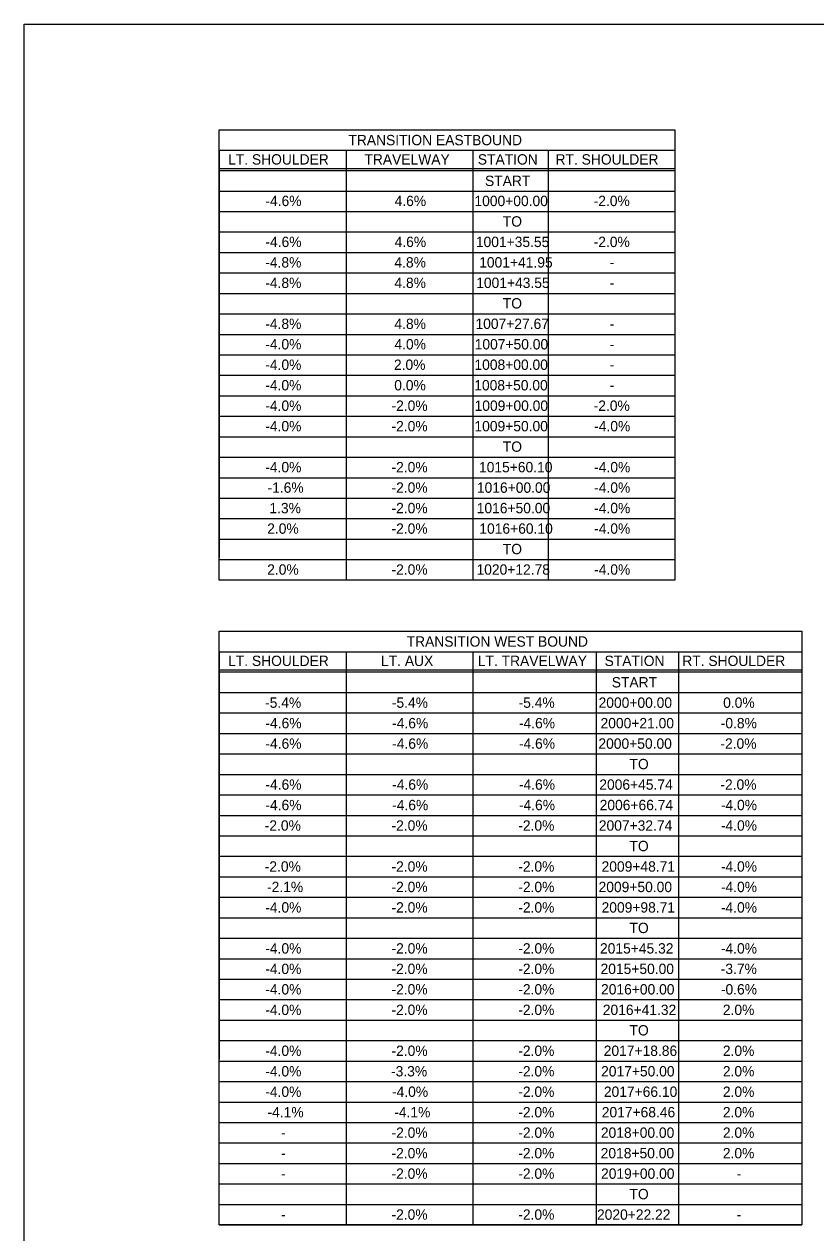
# Model space of a CAD drawing. Extents: x -15319374 to 1762012, y 465773 to 3693661.
# Drawn here: x -15314452.8 to -15314223.1, y 3693309.9 to 3693660.7 of the extents above; entities that cross this region are included whole.
import ezdxf

# ---------------------------------------------------------------- set-up
doc = ezdxf.new("R2010")
doc.units = 0
for name, color, linetype in [('BORDER', 7, 'Continuous'), ('Default', 7, 'Continuous'), ('DIMENSIONS', 7, 'Continuous')]:
    doc.layers.add(name, color=color, linetype=linetype)

msp = doc.modelspace()

# ---------------------------------------------------------------- linework, layer by layer
at = {"layer": 'BORDER'}
for p, q in [((-15314396.16, 3693624.08), (-15314396.16, 3693505.88)), ((-15314359.39, 3693624.08), (-15314359.39, 3693499.35)), ((-15314322.62, 3693624.08), (-15314322.62, 3693499.35)), ((-15314300.75, 3693624.08), (-15314300.75, 3693499.35)), ((-15314396.16, 3693618.8), (-15314263.98, 3693618.8)), ((-15314396.16, 3693618.2), (-15314263.98, 3693618.2)), ((-15314396.16, 3693612.26), (-15314263.98, 3693612.26)), ((-15314396.16, 3693612.26), (-15314263.98, 3693612.26)), ((-15314396.16, 3693612.26), (-15314263.98, 3693612.26)), ((-15314396.16, 3693606.32), (-15314263.98, 3693606.32)), ((-15314396.16, 3693600.38), (-15314263.98, 3693600.38)), ((-15314396.16, 3693594.43), (-15314263.98, 3693594.43)), ((-15314396.16, 3693588.49), (-15314263.98, 3693588.49)), ((-15314396.16, 3693582.55), (-15314263.98, 3693582.55)), ((-15314396.16, 3693576.6), (-15314263.98, 3693576.6)), ((-15314396.16, 3693570.66), (-15314263.98, 3693570.66)), ((-15314396.16, 3693564.72), (-15314263.98, 3693564.72)), ((-15314396.16, 3693558.78), (-15314263.98, 3693558.78)), ((-15314396.16, 3693552.83), (-15314263.98, 3693552.83)), ((-15314396.16, 3693546.89), (-15314263.98, 3693546.89)), ((-15314396.16, 3693540.95), (-15314263.98, 3693540.95)), ((-15314396.16, 3693535.01), (-15314263.98, 3693535.01)), ((-15314396.16, 3693529.06), (-15314263.98, 3693529.06)), ((-15314396.16, 3693523.12), (-15314263.98, 3693523.12)), ((-15314396.16, 3693517.18), (-15314263.98, 3693517.18)), ((-15314396.16, 3693511.24), (-15314263.98, 3693511.24)), ((-15314396.16, 3693505.29), (-15314263.98, 3693505.29)), ((-15314396.16, 3693478.56), (-15314396.16, 3693360.36)), ((-15314359.39, 3693478.56), (-15314359.39, 3693312.23)), ((-15314322.62, 3693478.56), (-15314322.62, 3693312.23)), ((-15314286.85, 3693478.56), (-15314286.85, 3693312.23)), ((-15314262.98, 3693478.56), (-15314262.98, 3693312.23)), ((-15314396.16, 3693473.28), (-15314227.21, 3693473.28)), ((-15314396.16, 3693472.68), (-15314227.21, 3693472.68)), ((-15314396.16, 3693466.74), (-15314227.21, 3693466.74)), ((-15314396.16, 3693466.74), (-15314227.21, 3693466.74)), ((-15314396.16, 3693466.74), (-15314227.21, 3693466.74)), ((-15314396.16, 3693460.8), (-15314227.21, 3693460.8)), ((-15314396.16, 3693454.85), (-15314227.21, 3693454.85)), ((-15314396.16, 3693448.91), (-15314227.21, 3693448.91)), ((-15314396.16, 3693442.97), (-15314227.21, 3693442.97)), ((-15314396.16, 3693437.02), (-15314227.21, 3693437.02)), ((-15314396.16, 3693431.08), (-15314227.21, 3693431.08)), ((-15314396.16, 3693425.14), (-15314227.21, 3693425.14)), ((-15314396.16, 3693419.2), (-15314227.21, 3693419.2)), ((-15314396.16, 3693413.25), (-15314227.21, 3693413.25)), ((-15314396.16, 3693407.31), (-15314227.21, 3693407.31)), ((-15314396.16, 3693401.37), (-15314227.21, 3693401.37)), ((-15314396.16, 3693395.43), (-15314227.21, 3693395.43)), ((-15314396.16, 3693389.48), (-15314227.21, 3693389.48)), ((-15314396.16, 3693383.54), (-15314227.21, 3693383.54)), ((-15314396.16, 3693377.6), (-15314227.21, 3693377.6)), ((-15314396.16, 3693371.66), (-15314227.21, 3693371.66)), ((-15314396.16, 3693365.71), (-15314227.21, 3693365.71)), ((-15314396.16, 3693359.77), (-15314227.21, 3693359.77)), ((-15314396.16, 3693353.83), (-15314227.21, 3693353.83)), ((-15314396.16, 3693347.88), (-15314227.21, 3693347.88)), ((-15314396.16, 3693341.94), (-15314227.21, 3693341.94)), ((-15314396.16, 3693336), (-15314227.21, 3693336)), ((-15314396.16, 3693330.06), (-15314227.21, 3693330.06)), ((-15314396.16, 3693324.11), (-15314227.21, 3693324.11)), ((-15314396.16, 3693318.17), (-15314227.21, 3693318.17)), ((-15314396.16, 3693312.23), (-15314227.21, 3693312.23))]:
    msp.add_line(p, q, dxfattribs=at)
for points in [[(-15314396.16, 3693624.08), (-15314396.16, 3693630.02), (-15314263.98, 3693630.02), (-15314263.98, 3693624.08)], [(-15314396.16, 3693478.56), (-15314396.16, 3693484.5), (-15314227.21, 3693484.5), (-15314227.21, 3693478.56)]]:
    msp.add_lwpolyline(points, dxfattribs=at)
for points in [[(-15314396.16, 3693624.08), (-15314263.98, 3693624.08), (-15314263.98, 3693499.35), (-15314396.16, 3693499.35)], [(-15314396.16, 3693478.56), (-15314227.21, 3693478.56), (-15314227.21, 3693312.23), (-15314396.16, 3693312.23)]]:
    msp.add_lwpolyline(points, close=True, dxfattribs=at)
at = {"layer": 'Default'}
msp.add_lwpolyline([(-15314452.76, 3693660.68), (-15313582.2, 3693660.68), (-15313582.2, 3693071.2), (-15314452.76, 3693071.2)], close=True, dxfattribs=at)

# ---------------------------------------------------------------- texts
at = {"layer": 'DIMENSIONS'}
for s, p in [('TRANSITION EASTBOUND', (-15314358.71, 3693625.55)), ('LT. SHOULDER', (-15314393.6, 3693619.94)), ('TRAVELWAY', (-15314354.06, 3693619.94)), ('STATION', (-15314321.16, 3693619.94)), ('RT. SHOULDER', (-15314298.62, 3693619.94)), ('START', (-15314319.08, 3693613.72)), ('-4.6%', (-15314382.78, 3693607.89)), ('4.6%', (-15314345.3, 3693607.89)), ('1000+00.00', (-15314322.14, 3693607.89)), ('-2.0%', (-15314287.56, 3693607.89)), ('TO', (-15314313.92, 3693601.94)), ('-4.6%', (-15314382.78, 3693596)), ('4.6%', (-15314345.3, 3693596)), ('1001+35.55', (-15314321.73, 3693596)), ('-2.0%', (-15314287.56, 3693596)), ('-4.8%', (-15314382.82, 3693590.06)), ('4.8%', (-15314345.35, 3693590.06)), ('1001+41.95', (-15314320.76, 3693590.06)), ('-', (-15314282.87, 3693590.06)), ('-4.8%', (-15314382.82, 3693584.12)), ('4.8%', (-15314345.35, 3693584.12)), ('1001+43.55', (-15314321.63, 3693584.12)), ('-', (-15314282.87, 3693584.12)), ('TO', (-15314313.92, 3693578.17)), ('-4.8%', (-15314382.82, 3693572.23)), ('4.8%', (-15314345.35, 3693572.23)), ('1007+27.67', (-15314321.84, 3693572.23)), ('-', (-15314282.87, 3693572.23)), ('-4.0%', (-15314382.82, 3693566.29)), ('4.0%', (-15314345.35, 3693566.29)), ('1007+50.00', (-15314322.07, 3693566.29)), ('-', (-15314282.87, 3693566.29)), ('-4.0%', (-15314382.82, 3693560.35)), ('2.0%', (-15314345.49, 3693560.35)), ('1008+00.00', (-15314322.14, 3693560.35)), ('-', (-15314282.87, 3693560.35)), ('-4.0%', (-15314382.82, 3693554.4)), ('0.0%', (-15314345.4, 3693554.4)), ('1008+50.00', (-15314322.19, 3693554.4)), ('-', (-15314282.87, 3693554.4)), ('-4.0%', (-15314382.82, 3693548.46)), ('-2.0%', (-15314346.2, 3693548.46)), ('1009+00.00', (-15314322.1, 3693548.46)), ('-2.0%', (-15314287.56, 3693548.46)), ('-4.0%', (-15314382.82, 3693542.52)), ('-2.0%', (-15314346.2, 3693542.52)), ('1009+50.00', (-15314322.14, 3693542.52)), ('-4.0%', (-15314287.41, 3693542.52)), ('TO', (-15314313.92, 3693536.58)), ('-4.0%', (-15314382.82, 3693530.63)), ('-2.0%', (-15314346.2, 3693530.63)), ('1015+60.10', (-15314320.82, 3693530.63)), ('-4.0%', (-15314287.41, 3693530.63)), ('-1.6%', (-15314382.16, 3693524.69)), ('-2.0%', (-15314346.2, 3693524.69)), ('1016+00.00', (-15314321.43, 3693524.69)), ('-4.0%', (-15314287.41, 3693524.69)), ('1.3%', (-15314381.62, 3693518.75)), ('-2.0%', (-15314346.2, 3693518.75)), ('1016+50.00', (-15314321.48, 3693518.75)), ('-4.0%', (-15314287.41, 3693518.75)), ('2.0%', (-15314382.26, 3693512.8)), ('-2.0%', (-15314346.2, 3693512.8)), ('1016+60.10', (-15314320.72, 3693512.8)), ('-4.0%', (-15314287.41, 3693512.8)), ('TO', (-15314313.92, 3693506.86)), ('2.0%', (-15314382.26, 3693500.92)), ('-2.0%', (-15314346.2, 3693500.92)), ('1020+12.78', (-15314321.54, 3693500.92)), ('-4.0%', (-15314287.41, 3693500.92)), ('TRANSITION WEST BOUND', (-15314341.81, 3693480.03)), ('LT. SHOULDER', (-15314393.6, 3693474.42)), ('LT. AUX', (-15314349.24, 3693474.42)), ('LT. TRAVELWAY', (-15314321.17, 3693474.42)), ('STATION', (-15314284.39, 3693474.42)), ('RT. SHOULDER', (-15314261.85, 3693474.42)), ('START', (-15314282.31, 3693468.19)), ('-5.4%', (-15314382.87, 3693462.28)), ('-5.4%', (-15314346.1, 3693462.28)), ('-5.4%', (-15314309.34, 3693462.28)), ('2000+00.00', (-15314286.13, 3693462.28)), ('0.0%', (-15314249.99, 3693462.28)), ('-4.6%', (-15314382.78, 3693456.34)), ('-4.6%', (-15314346.01, 3693456.34)), ('-4.6%', (-15314309.24, 3693456.34)), ('2000+21.00', (-15314285.56, 3693456.34)), ('-0.8%', (-15314250.69, 3693456.34)), ('-4.6%', (-15314382.78, 3693450.4)), ('-4.6%', (-15314346.01, 3693450.4)), ('-4.6%', (-15314309.24, 3693450.4)), ('2000+50.00', (-15314286.18, 3693450.4)), ('-2.0%', (-15314250.79, 3693450.4)), ('TO', (-15314277.16, 3693444.46)), ('-4.6%', (-15314382.78, 3693438.51)), ('-4.6%', (-15314346.01, 3693438.51)), ('-4.6%', (-15314309.24, 3693438.51)), ('2006+45.74', (-15314285.92, 3693438.51)), ('-2.0%', (-15314250.79, 3693438.51)), ('-4.6%', (-15314382.78, 3693432.57)), ('-4.6%', (-15314346.01, 3693432.57)), ('-4.6%', (-15314309.24, 3693432.57)), ('2006+66.74', (-15314285.82, 3693432.57)), ('-4.0%', (-15314250.65, 3693432.57)), ('-2.0%', (-15314382.97, 3693426.63)), ('-2.0%', (-15314346.2, 3693426.63)), ('-2.0%', (-15314309.43, 3693426.63)), ('2007+32.74', (-15314286.06, 3693426.63)), ('-4.0%', (-15314250.65, 3693426.63)), ('TO', (-15314277.16, 3693420.68)), ('-2.0%', (-15314382.97, 3693414.74)), ('-2.0%', (-15314346.2, 3693414.74)), ('-2.0%', (-15314309.43, 3693414.74)), ('2009+48.71', (-15314285.26, 3693414.74)), ('-4.0%', (-15314250.65, 3693414.74)), ('-2.1%', (-15314382.31, 3693408.8)), ('-2.0%', (-15314346.2, 3693408.8)), ('-2.0%', (-15314309.43, 3693408.8)), ('2009+50.00', (-15314286.13, 3693408.8)), ('-4.0%', (-15314250.65, 3693408.8)), ('-4.0%', (-15314382.82, 3693402.86)), ('-2.0%', (-15314346.2, 3693402.86)), ('-2.0%', (-15314309.43, 3693402.86)), ('2009+98.71', (-15314285.26, 3693402.86)), ('-4.0%', (-15314250.65, 3693402.86)), ('TO', (-15314277.16, 3693396.91)), ('-4.0%', (-15314382.82, 3693390.97)), ('-2.0%', (-15314346.2, 3693390.97)), ('-2.0%', (-15314309.43, 3693390.97)), ('2015+45.32', (-15314285.72, 3693390.97)), ('-4.0%', (-15314250.65, 3693390.97)), ('-4.0%', (-15314382.82, 3693385.03)), ('-2.0%', (-15314346.2, 3693385.03)), ('-2.0%', (-15314309.43, 3693385.03)), ('2015+50.00', (-15314285.56, 3693385.03)), ('-3.7%', (-15314250.69, 3693385.03)), ('-4.0%', (-15314382.82, 3693379.09)), ('-2.0%', (-15314346.2, 3693379.09)), ('-2.0%', (-15314309.43, 3693379.09)), ('2016+00.00', (-15314285.42, 3693379.09)), ('-0.6%', (-15314250.65, 3693379.09)), ('-4.0%', (-15314382.82, 3693373.14)), ('-2.0%', (-15314346.2, 3693373.14)), ('-2.0%', (-15314309.43, 3693373.14)), ('2016+41.32', (-15314284.91, 3693373.14)), ('2.0%', (-15314250.08, 3693373.14)), ('TO', (-15314277.16, 3693367.2)), ('-4.0%', (-15314382.82, 3693361.26)), ('-2.0%', (-15314346.2, 3693361.26)), ('-2.0%', (-15314309.43, 3693361.26)), ('2017+18.86', (-15314284.64, 3693361.26)), ('2.0%', (-15314250.08, 3693361.26)), ('-4.0%', (-15314382.82, 3693355.31)), ('-3.3%', (-15314346.34, 3693355.31)), ('-2.0%', (-15314309.43, 3693355.31)), ('2017+50.00', (-15314285.4, 3693355.31)), ('2.0%', (-15314250.08, 3693355.31)), ('-4.0%', (-15314382.82, 3693349.37)), ('-4.0%', (-15314346.06, 3693349.37)), ('-2.0%', (-15314309.43, 3693349.37)), ('2017+66.10', (-15314284.6, 3693349.37)), ('2.0%', (-15314250.08, 3693349.37)), ('-4.1%', (-15314382.16, 3693343.43)), ('-4.1%', (-15314345.4, 3693343.43)), ('-2.0%', (-15314309.43, 3693343.43)), ('2017+68.46', (-15314285.21, 3693343.43)), ('2.0%', (-15314250.08, 3693343.43)), ('-', (-15314378.28, 3693337.49)), ('-2.0%', (-15314346.2, 3693337.49)), ('-2.0%', (-15314309.43, 3693337.49)), ('2018+00.00', (-15314285.47, 3693337.49)), ('2.0%', (-15314250.08, 3693337.49)), ('-2.0%', (-15314346.2, 3693331.54)), ('-2.0%', (-15314309.43, 3693331.54)), ('2018+50.00', (-15314285.52, 3693331.54)), ('2.0%', (-15314250.08, 3693331.54)), ('-', (-15314378.28, 3693331.54)), ('-', (-15314378.28, 3693325.6)), ('-2.0%', (-15314346.2, 3693325.6)), ('-2.0%', (-15314309.43, 3693325.6)), ('2019+00.00', (-15314285.42, 3693325.6)), ('-', (-15314246.1, 3693325.6)), ('TO', (-15314277.16, 3693319.66)), ('-2.0%', (-15314346.2, 3693313.72)), ('-2.0%', (-15314309.43, 3693313.72)), ('2020+22.22', (-15314286.59, 3693313.72)), ('-', (-15314378.28, 3693313.72)), ('-', (-15314246.1, 3693313.72))]:
    msp.add_text(s, height=3, dxfattribs=at).set_placement(p)

doc.saveas('drawing.dxf')
